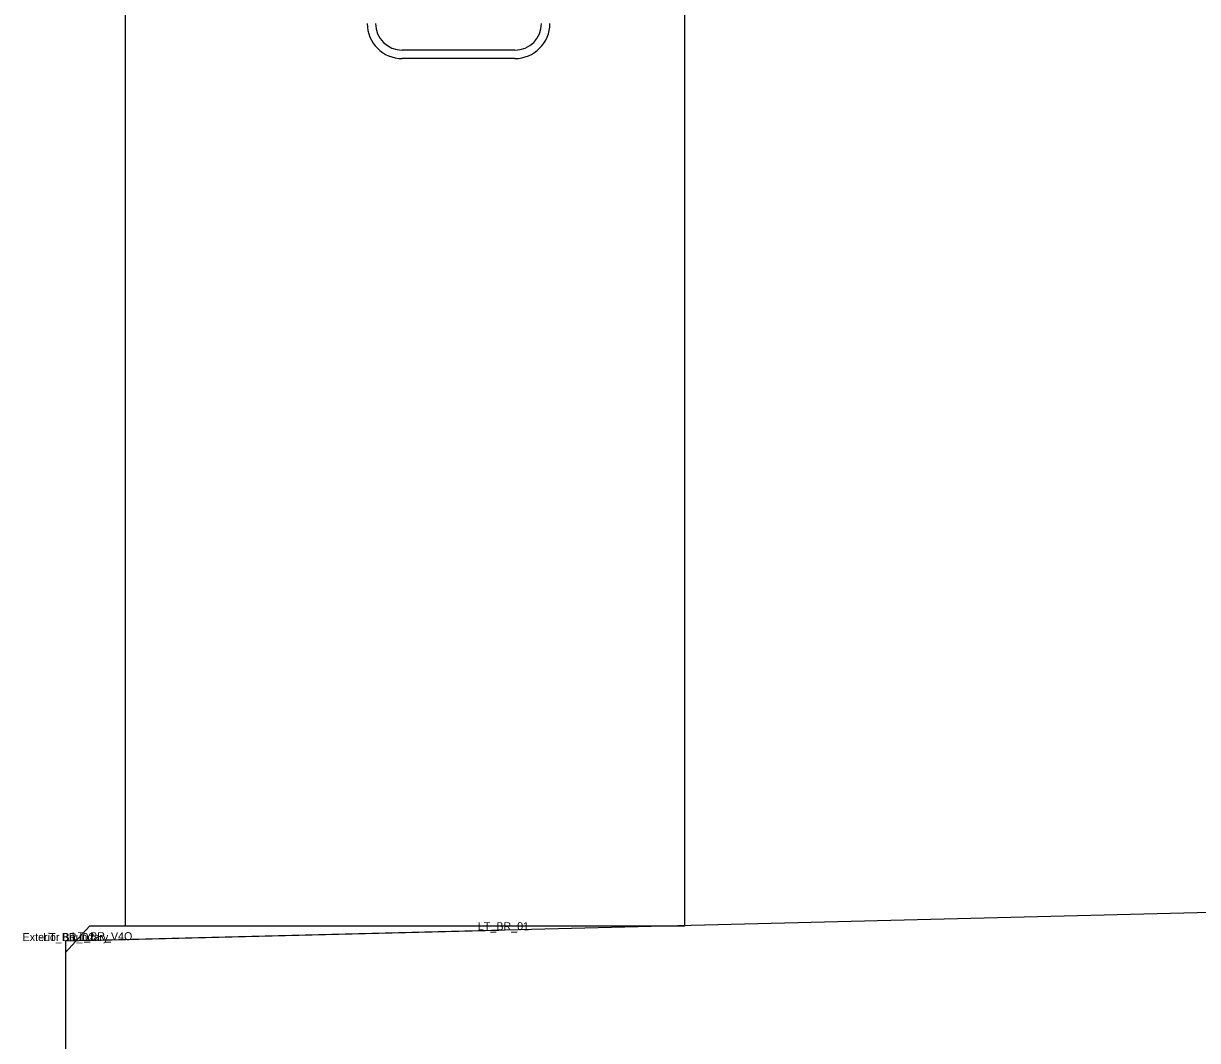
# Model space of a CAD drawing. Extents: x -26 to 4903, y -1010 to 9587.
# Drawn here: x 1109.687 to 1112.621, y 3542.974 to 3545.515 of the extents above; entities that cross this region are included whole.
import ezdxf

# ---------------------------------------------------------------- set-up
doc = ezdxf.new("R2010")
doc.units = 0
for name, color, linetype in [('Default', 7, 'Continuous'), ('Prop CMT Concrete Structures', 7, 'Continuous'), ('Typical Bridge Rail Two Bar CELL', 7, 'Continuous')]:
    doc.layers.add(name, color=color, linetype=linetype)

msp = doc.modelspace()

# ---------------------------------------------------------------- linework, layer by layer
at = {"layer": 'Default'}
for p, q in [((1109.9412, 3546.1903), (1109.9412, 3543.2592)), ((1111.3388, 3546.1903), (1111.3388, 3543.2592)), ((1110.9152, 3545.4486), (1110.6337, 3545.4486)), ((1110.9152, 3545.4277), (1110.6337, 3545.4277)), ((1109.7912, 3543.1927), (1109.8518, 3543.2592)), ((1109.953, 3543.2592), (1109.8518, 3543.2592)), ((1111.3388, 3543.2592), (1109.953, 3543.2592))]:
    msp.add_line(p, q, dxfattribs=at)
for points in [[(1150, 3544.2274), (1132, 3543.7774), (1109.7917, 3543.2222)], [(1109.875, 3543.2243), (1110.875, 3543.2493)], [(1109.7917, 3543.2222), (1109.7917, 3541.7222)]]:
    msp.add_lwpolyline(points, dxfattribs=at)
for centre, radius, start, end in [((1110.6337, 3545.515), 0.0876, 180, 270), ((1110.6337, 3545.5151), 0.0667, 180, 270), ((1110.915, 3545.5151), 0.0667, 270, 0), ((1110.9151, 3545.515), 0.0876, 270, 0)]:
    msp.add_arc(centre, radius, start, end, dxfattribs=at)
at = {"layer": 'Prop CMT Concrete Structures'}
for p, q in [((1132, 3543.7774), (1109.7917, 3543.2222)), ((1109.875, 3543.2243), (1110.875, 3543.2493)), ((1109.7917, 3543.2222), (1109.7917, 3541.7222))]:
    msp.add_line(p, q, dxfattribs=at)
at = {"layer": 'Typical Bridge Rail Two Bar CELL'}
for p, q in [((1109.9412, 3546.1903), (1109.9412, 3543.2592)), ((1111.3388, 3546.1903), (1111.3388, 3543.2592)), ((1110.9152, 3545.4486), (1110.6337, 3545.4486)), ((1110.9152, 3545.4277), (1110.6337, 3545.4277)), ((1109.7912, 3543.1927), (1109.8518, 3543.2592)), ((1109.953, 3543.2592), (1109.8518, 3543.2592)), ((1111.3388, 3543.2592), (1109.953, 3543.2592))]:
    msp.add_line(p, q, dxfattribs=at)
for centre, radius, start, end in [((1110.6337, 3545.515), 0.0876, 180, 270), ((1110.6337, 3545.5151), 0.0667, 180, 270), ((1110.915, 3545.5151), 0.0667, 270, 0), ((1110.9151, 3545.515), 0.0876, 270, 0)]:
    msp.add_arc(centre, radius, start, end, dxfattribs=at)

# ---------------------------------------------------------------- texts
at = {"layer": 'Default'}
for s, p in [('LT_BR_01', (1110.8227, 3543.2493)), ('Exterior Boundary', (1109.6849, 3543.2222)), ('LT_BR_02', (1109.7364, 3543.2222)), ('LT_BR_V4O', (1109.8076, 3543.2243))]:
    msp.add_text(s, height=0.02, dxfattribs=at).set_placement(p)

doc.saveas('drawing.dxf')
